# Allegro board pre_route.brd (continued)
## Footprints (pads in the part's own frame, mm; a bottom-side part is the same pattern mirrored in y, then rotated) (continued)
HDR2X2_100MIL
  round 1.651 hole 1.067: 1(0,0) 2(0,2.54) 3(2.54,0) 4(2.54,2.54)
HDR2X4_100MIL
  round 1.651 hole 1.067: 1(0,0) 2(0,2.54) 3(2.54,0) 4(2.54,2.54) 5(5.08,0) 6(5.08,2.54) 7(7.62,0) 8(7.62,2.54)
HDR2X7_100MIL
  rect 3.175x1.27 smd: 1(-2.731,7.62) 2(2.731,7.62) 3(-2.731,5.08) 4(2.731,5.08) 5(-2.731,2.54) 6(2.731,2.54) 7(-2.731,0) 8(2.731,0) 9(-2.731,-2.54) 10(2.731,-2.54) 11(-2.731,-5.08) 12(2.731,-5.08) 13(-2.731,-7.62) 14(2.731,-7.62)
HDR2X10_100MIL
  rect 3.175x1.27 smd: 1(-2.731,11.43) 2(2.731,11.43) 3(-2.731,8.89) 4(2.731,8.89) 5(-2.731,6.35) 6(2.731,6.35) 7(-2.731,3.81) 8(2.731,3.81) 9(-2.731,1.27) 10(2.731,1.27) 11(-2.731,-1.27) 12(2.731,-1.27) 13(-2.731,-3.81) 14(2.731,-3.81) 15(-2.731,-6.35) 16(2.731,-6.35) 17(-2.731,-8.89) 18(2.731,-8.89) 19(-2.731,-11.43) 20(2.731,-11.43)
HDR2X20_100MIL
  rect 3.175x1.27 smd: 1(-2.731,24.13) 2(2.731,24.13) 3(-2.731,21.59) 4(2.731,21.59) 5(-2.731,19.05) 6(2.731,19.05) 7(-2.731,16.51) 8(2.731,16.51) 9(-2.731,13.97) 10(2.731,13.97) 11(-2.731,11.43) 12(2.731,11.43) 13(-2.731,8.89) 14(2.731,8.89) 15(-2.731,6.35) 16(2.731,6.35) 17(-2.731,3.81) 18(2.731,3.81) 19(-2.731,1.27) 20(2.731,1.27) 21(-2.731,-1.27) 22(2.731,-1.27) 23(-2.731,-3.81) 24(2.731,-3.81) 25(-2.731,-6.35) 26(2.731,-6.35) 27(-2.731,-8.89) 28(2.731,-8.89) 29(-2.731,-11.43) 30(2.731,-11.43) 31(-2.731,-13.97) 32(2.731,-13.97) 33(-2.731,-16.51) 34(2.731,-16.51) 35(-2.731,-19.05) 36(2.731,-19.05) 37(-2.731,-21.59) 38(2.731,-21.59) 39(-2.731,-24.13) 40(2.731,-24.13)
HEATSINK-7106D
  custom 2.603x2.603 smd: 1(0,0)
HSSDC2
  round 0.127 hole 2.184 unplated: (-1.825,3.2) (-1.825,-3.2)
  rect 1.524x0.813 smd: 1(-10.325,3.81) 2(-10.325,2.54) 3(-10.325,1.27) 4(-10.325,0) 5(-10.325,-1.27) 6(-10.325,-2.54) 7(-10.325,-3.81)
  rect 4.013x2.54 hole 1.575: 8(-9.025,6.125) 9(-9.025,-6.125) 10(-1.825,6.125) 11(-1.825,-6.125)
  rect 3.023x3.124 hole 1.575: 12(0.975,2.6) 13(0.975,-2.6)
LQFP_32
  rect 1.905x0.457 smd: 1(-4.242,2.8) 2(-4.242,2) 3(-4.242,1.2) 4(-4.242,0.4) 5(-4.242,-0.4) 6(-4.242,-1.2) 7(-4.242,-2) 8(-4.242,-2.8) 17(4.242,-2.8) 18(4.242,-2) 19(4.242,-1.2) 20(4.242,-0.4) 21(4.242,0.4) 22(4.242,1.2) 23(4.242,2) 24(4.242,2.8)
  rect 0.457x1.905 smd: 9(-2.8,-4.242) 10(-2,-4.242) 11(-1.2,-4.242) 12(-0.4,-4.242) 13(0.4,-4.242) 14(1.2,-4.242) 15(2,-4.242) 16(2.8,-4.242) 25(2.8,4.242) 26(2,4.242) 27(1.2,4.242) 28(0.4,4.242) 29(-0.4,4.242) 30(-1.2,4.242) 31(-2,4.242) 32(-2.8,4.242)
MICTOR
  round 0.127 hole 0.813 unplated: (-15.113,-1.016) (15.113,0)
  round 0.127 hole 2.388 unplated: (11.43,0)
  rect 0.432x1.651 smd: 1(5.715,3.531) 2(5.715,-3.531) 3(5.08,3.531) 4(5.08,-3.531) 5(4.445,3.531) 6(4.445,-3.531) 7(3.81,3.531) 8(3.81,-3.531) 9(3.175,3.531) 10(3.175,-3.531) 11(2.54,3.531) 12(2.54,-3.531) 13(1.905,3.531) 14(1.905,-3.531) 15(1.27,3.531) 16(1.27,-3.531) 17(0.635,3.531) 18(0.635,-3.531) 19(0,3.531) 20(0,-3.531) 21(-0.635,3.531) 22(-0.635,-3.531) 23(-1.27,3.531) 24(-1.27,-3.531) 25(-1.905,3.531) 26(-1.905,-3.531) 27(-2.54,3.531) 28(-2.54,-3.531) 29(-3.175,3.531) 30(-3.175,-3.531) 31(-3.81,3.531) 32(-3.81,-3.531) 33(-4.445,3.531) 34(-4.445,-3.531) 35(-5.08,3.531) 36(-5.08,-3.531) 37(-5.715,3.531) 38(-5.715,-3.531)
  round 1.321 hole 0.813: 39(5.08,0) 40(2.54,0) 41(0,0) 42(-2.54,0) 43(-5.08,0)
MOLEX-10X2
  round 0.127 hole 2.997 unplated: (-42.456,5.055) (4.737,5.055)
  rect 1.905x1.905 hole 1.422: 1(0,0)
  round 1.905 hole 1.422: 2(-4.191,0) 3(-8.382,0) 4(-12.573,0) 5(-16.764,0) 6(-20.955,0) 7(-25.146,0) 8(-29.337,0) 9(-33.528,0) 10(-37.719,0) 11(0,5.512) 12(-4.191,5.512) 13(-8.382,5.512) 14(-12.573,5.512) 15(-16.764,5.512) 16(-20.955,5.512) 17(-25.146,5.512) 18(-29.337,5.512) 19(-33.528,5.512) 20(-37.719,5.512)
PACKAGE_D
  rect 2.007x1.803 smd: 1(-2.1,2.54) 2(-2.1,0) 3(-2.1,-2.54) 4(2.1,-2.54) 5(2.1,0) 6(2.1,2.54)
PQFP100_720X956
  rect 2.54x0.406 smd: 1(-8.382,9.425) 2(-8.382,8.775) 3(-8.382,8.125) 4(-8.382,7.475) 5(-8.382,6.825) 6(-8.382,6.175) 7(-8.382,5.525) 8(-8.382,4.875) 9(-8.382,4.225) 10(-8.382,3.575) 11(-8.382,2.925) 12(-8.382,2.275) 13(-8.382,1.625) 14(-8.382,0.975) 15(-8.382,0.325) 16(-8.382,-0.325) 17(-8.382,-0.975) 18(-8.382,-1.625) 19(-8.382,-2.275) 20(-8.382,-2.925) 21(-8.382,-3.575) 22(-8.382,-4.225) 23(-8.382,-4.875) 24(-8.382,-5.525) 25(-8.382,-6.175) 26(-8.382,-6.825) 27(-8.382,-7.475) 28(-8.382,-8.125) 29(-8.382,-8.775) 30(-8.382,-9.425) 51(8.382,-9.425) 52(8.382,-8.775) 53(8.382,-8.125) 54(8.382,-7.475) 55(8.382,-6.825) 56(8.382,-6.175) 57(8.382,-5.525) 58(8.382,-4.875) 59(8.382,-4.225) 60(8.382,-3.575) 61(8.382,-2.925) 62(8.382,-2.275) 63(8.382,-1.625) 64(8.382,-0.975) 65(8.382,-0.325) 66(8.382,0.325) 67(8.382,0.975) 68(8.382,1.625) 69(8.382,2.275) 70(8.382,2.925) 71(8.382,3.575) 72(8.382,4.225) 73(8.382,4.875) 74(8.382,5.525) 75(8.382,6.175) 76(8.382,6.825) 77(8.382,7.475) 78(8.382,8.125) 79(8.382,8.775) 80(8.382,9.425)
  rect 0.406x2.54 smd: 31(-6.175,-11.379) 32(-5.525,-11.379) 33(-4.875,-11.379) 34(-4.225,-11.379) 35(-3.575,-11.379) 36(-2.925,-11.379) 37(-2.275,-11.379) 38(-1.625,-11.379) 39(-0.975,-11.379) 40(-0.325,-11.379) 41(0.325,-11.379) 42(0.975,-11.379) 43(1.625,-11.379) 44(2.275,-11.379) 45(2.925,-11.379) 46(3.575,-11.379) 47(4.225,-11.379) 48(4.875,-11.379) 49(5.525,-11.379) 50(6.175,-11.379) 81(6.175,11.379) 82(5.525,11.379) 83(4.875,11.379) 84(4.225,11.379) 85(3.575,11.379) 86(2.925,11.379) 87(2.275,11.379) 88(1.625,11.379) 89(0.975,11.379) 90(0.325,11.379) 91(-0.325,11.379) 92(-0.975,11.379) 93(-1.625,11.379) 94(-2.275,11.379) 95(-2.925,11.379) 96(-3.575,11.379) 97(-4.225,11.379) 98(-4.875,11.379) 99(-5.525,11.379) 100(-6.175,11.379)
QSOP16
  rect 1.524x0.33 smd: 1(-2.413,2.223) 2(-2.413,1.587) 3(-2.413,0.953) 4(-2.413,0.318) 5(-2.413,-0.318) 6(-2.413,-0.953) 7(-2.413,-1.587) 8(-2.413,-2.223) 9(2.413,-2.223) 10(2.413,-1.587) 11(2.413,-0.953) 12(2.413,-0.318) 13(2.413,0.318) 14(2.413,0.953) 15(2.413,1.587) 16(2.413,2.223)
RES_0402
  rect 0.508x0.508 smd: 1(0,0.445) 2(0,-0.445)
RES_0603
  rect 0.813x1.067 smd: 1(0,0.85) 2(0,-0.85)
RES_0805
  rect 1.6x1.321 smd: 1(0,0.95) 2(0,-0.95)
RJ426
  round 0.127 hole 3.2 unplated: (-10.16,6.35) (1.27,6.35)
  rect 1.397x1.397 hole 0.914: 1(0,0)
  round 1.397 hole 0.914: 2(-1.27,-2.54) 3(-2.54,0) 4(-3.81,-2.54) 5(-5.08,0) 6(-6.35,-2.54) 7(-7.62,0) 8(-8.89,-2.54)
  round 1.524 hole 1.067: 9(2.184,10.414) 10(-0.356,10.414) 11(-8.534,10.414) 12(-11.074,10.414)
  round 2.083 hole 1.575: 13(-12.192,3.302) 14(3.302,3.302)
RN_SMT
  rect 0.889x0.432 smd: 1(-0.817,1.839) 8(-0.817,-1.839) 9(0.817,-1.839) 16(0.817,1.839)
  rect 0.889x0.254 smd: 2(-0.817,1.25) 3(-0.817,0.75) 4(-0.817,0.25) 5(-0.817,-0.25) 6(-0.817,-0.75) 7(-0.817,-1.25) 10(0.817,-1.25) 11(0.817,-0.75) 12(0.817,-0.25) 13(0.817,0.25) 14(0.817,0.75) 15(0.817,1.25)
RPACK8
  rect 0.889x0.432 smd: 1(-0.944,1.839) 8(-0.944,-1.839) 9(0.944,-1.839) 16(0.944,1.839)
  rect 0.889x0.254 smd: 2(-0.944,1.25) 3(-0.944,0.75) 4(-0.944,0.25) 5(-0.944,-0.25) 6(-0.944,-0.75) 7(-0.944,-1.25) 10(0.944,-1.25) 11(0.944,-0.75) 12(0.944,-0.25) 13(0.944,0.25) 14(0.944,0.75) 15(0.944,1.25)
SFP
  round 0.127 hole 1.575 unplated: (-1.4,4.1) (8.2,4.1)
  rect 0.533x2.007 smd: 1(0,0) 2(0.8,0) 3(1.6,0) 4(2.4,0) 5(3.2,0) 6(4,0) 7(4.8,0) 8(5.6,0) 9(6.4,0) 10(7.2,0) 11(6.8,8.2) 12(6,8.2) 13(5.2,8.2) 14(4.4,8.2) 15(3.6,8.2) 16(2.8,8.2) 17(2,8.2) 18(1.2,8.2) 19(0.4,8.2) 20(-0.4,8.2)
  rect 1.981x1.981 hole 1.067: 21(-3.721,-26.765) 22(4.864,-26.765) 23(10.503,-21.765) 24(-3.721,-16.765) 25(10.503,-11.765) 26(7.353,-6.765) 27(1.968,-6.765) 28(-3.721,-6.765) 31(10.503,-1.765) 37(10.503,8.235)
  round 1.473 hole 1.067: 29(-3.721,-3.965) 30(10.503,-3.965) 32(-3.721,0.735) 33(10.503,0.735) 35(-3.721,5.735) 36(10.503,5.735) 38(-1.409,10.335) 39(3.391,10.335) 40(8.191,10.335)
  rect 1.981x1.981 hole 0.914: 34(-3.721,3.235)
SMT
  round 0.127 hole 1.397 unplated: (-17.2,0) (17.2,0)
  rect 0.61x2.108 smd: 1(-15.5,-1.95) 2(-15.5,1.95) 3(-14.5,-1.95) 4(-14.5,1.95) 5(-13.5,-1.95) 6(-13.5,1.95) 7(-12.5,-1.95) 8(-12.5,1.95) 9(-11.5,-1.95) 10(-11.5,1.95) 11(-10.5,-1.95) 12(-10.5,1.95) 13(-9.5,-1.95) 14(-9.5,1.95) 15(-8.5,-1.95) 16(-8.5,1.95) 17(-7.5,-1.95) 18(-7.5,1.95) 19(-6.5,-1.95) 20(-6.5,1.95) 21(-5.5,-1.95) 22(-5.5,1.95) 23(-4.5,-1.95) 24(-4.5,1.95) 25(-3.5,-1.95) 26(-3.5,1.95) 27(-2.5,-1.95) 28(-2.5,1.95) 29(-1.5,-1.95) 30(-1.5,1.95) 31(-0.5,-1.95) 32(-0.5,1.95) 33(0.5,-1.95) 34(0.5,1.95) 35(1.5,-1.95) 36(1.5,1.95) 37(2.5,-1.95) 38(2.5,1.95) 39(3.5,-1.95) 40(3.5,1.95) 41(4.5,-1.95) 42(4.5,1.95) 43(5.5,-1.95) 44(5.5,1.95) 45(6.5,-1.95) 46(6.5,1.95) 47(7.5,-1.95) 48(7.5,1.95) 49(8.5,-1.95) 50(8.5,1.95) 51(9.5,-1.95) 52(9.5,1.95) 53(10.5,-1.95) 54(10.5,1.95) 55(11.5,-1.95) 56(11.5,1.95) 57(12.5,-1.95) 58(12.5,1.95) 59(13.5,-1.95) 60(13.5,1.95) 61(14.5,-1.95) 62(14.5,1.95) 63(15.5,-1.95) 64(15.5,1.95)
SMT_A_PROBE
  round 1.346 hole 0.813: (-14.981,2.413) (-14.981,-2.413) (14.991,-2.413)
  round 0.127 hole 0.813 unplated: (-14.981,0) (14.991,2.413)
  oval 0.584x0.711 smd: A1(-13,-1.27) A2(-12,-1.27) A3(-11,-1.27) A4(-10,-1.27) A5(-9,-1.27) A6(-8,-1.27) A7(-7,-1.27) A8(-6,-1.27) A9(-5,-1.27) A10(-4,-1.27) A11(-3,-1.27) A12(-2,-1.27) A13(-1,-1.27) A14(0,-1.27) A15(1,-1.27) A16(2,-1.27) A17(3,-1.27) A18(4,-1.27) A19(5,-1.27) A20(6,-1.27) A21(7,-1.27) A22(8,-1.27) A23(9,-1.27) A24(10,-1.27) A25(11,-1.27) A26(12,-1.27) A27(13,-1.27) B1(-13,1.27) B2(-12,1.27) B3(-11,1.27) B4(-10,1.27) B5(-9,1.27) B6(-8,1.27) B7(-7,1.27) B8(-6,1.27) B9(-5,1.27) B10(-4,1.27) B11(-3,1.27) B12(-2,1.27) B13(-1,1.27) B14(0,1.27) B15(1,1.27) B16(2,1.27) B17(3,1.27) B18(4,1.27) B19(5,1.27) B20(6,1.27) B21(7,1.27) B22(8,1.27) B23(9,1.27) B24(10,1.27) B25(11,1.27) B26(12,1.27) B27(13,1.27)
SO8
  oval 2.032x0.635 smd: 1(-2.54,1.905) 2(-2.54,0.635) 3(-2.54,-0.635) 4(-2.54,-1.905) 5(2.54,-1.905) 6(2.54,-0.635) 7(2.54,0.635) 8(2.54,1.905)
SO8N
  rect 0.584x2.184 smd: 1(0,-2.608) 2(1.27,-2.608) 3(2.54,-2.608) 4(3.81,-2.608) 5(3.81,2.608) 6(2.54,2.608) 7(1.27,2.608) 8(0,2.608)
SO24
  rect 2.184x0.813 smd: 1(-4.801,6.985) 2(-4.801,5.715) 3(-4.801,4.445) 4(-4.801,3.175) 5(-4.801,1.905) 6(-4.801,0.635) 7(-4.801,-0.635) 8(-4.801,-1.905) 9(-4.801,-3.175) 10(-4.801,-4.445) 11(-4.801,-5.715) 12(-4.801,-6.985) 13(4.801,-6.985) 14(4.801,-5.715) 15(4.801,-4.445) 16(4.801,-3.175) 17(4.801,-1.905) 18(4.801,-0.635) 19(4.801,0.635) 20(4.801,1.905) 21(4.801,3.175) 22(4.801,4.445) 23(4.801,5.715) 24(4.801,6.985)
SO40
  rect 1.803x0.305 smd: 1(-2.7,4.75) 2(-2.7,4.25) 3(-2.7,3.75) 4(-2.7,3.25) 5(-2.7,2.75) 6(-2.7,2.25) 7(-2.7,1.75) 8(-2.7,1.25) 9(-2.7,0.75) 10(-2.7,0.25) 11(-2.7,-0.25) 12(-2.7,-0.75) 13(-2.7,-1.25) 14(-2.7,-1.75) 15(-2.7,-2.25) 16(-2.7,-2.75) 17(-2.7,-3.25) 18(-2.7,-3.75) 19(-2.7,-4.25) 20(-2.7,-4.75) 21(2.7,-4.75) 22(2.7,-4.25) 23(2.7,-3.75) 24(2.7,-3.25) 25(2.7,-2.75) 26(2.7,-2.25) 27(2.7,-1.75) 28(2.7,-1.25) 29(2.7,-0.75) 30(2.7,-0.25) 31(2.7,0.25) 32(2.7,0.75) 33(2.7,1.25) 34(2.7,1.75) 35(2.7,2.25) 36(2.7,2.75) 37(2.7,3.25) 38(2.7,3.75) 39(2.7,4.25) 40(2.7,4.75)
SOG_05
  rect 1.499x0.305 smd: 1(-2.036,1) 2(-2.036,0.5) 3(-2.036,0) 4(-2.036,-0.5) 5(-2.036,-1) 6(2.036,-1) 7(2.036,-0.5) 8(2.036,0) 9(2.036,0.5) 10(2.036,1)
SOG_50
  rect 2.21x0.61 smd: 1(-2.6,4.445) 2(-2.6,3.175) 3(-2.6,1.905) 4(-2.6,0.635) 5(-2.6,-0.635) 6(-2.6,-1.905) 7(-2.6,-3.175) 8(-2.6,-4.445) 9(2.6,-4.445) 10(2.6,-3.175) 11(2.6,-1.905) 12(2.6,-0.635) 13(2.6,0.635) 14(2.6,1.905) 15(2.6,3.175) 16(2.6,4.445)
SOG_65
  rect 2.032x0.635 smd: 1(-2.794,1.905) 2(-2.794,0.635) 3(-2.794,-0.635) 4(-2.794,-1.905) 5(2.794,-1.905) 6(2.794,-0.635) 7(2.794,0.635) 8(2.794,1.905)
SOIC8
  rect 2.032x0.635 smd: 1(-2.794,1.905) 2(-2.794,0.635) 3(-2.794,-0.635) 4(-2.794,-1.905) 5(2.794,-1.905) 6(2.794,-0.635) 7(2.794,0.635) 8(2.794,1.905)
SOIC16F
  oval 2.032x0.635 smd: 1(-3.81,4.445) 2(-3.81,3.175) 3(-3.81,1.905) 4(-3.81,0.635) 5(-3.81,-0.635) 6(-3.81,-1.905) 7(-3.81,-3.175) 8(-3.81,-4.445) 9(3.81,-4.445) 10(3.81,-3.175) 11(3.81,-1.905) 12(3.81,-0.635) 13(3.81,0.635) 14(3.81,1.905) 15(3.81,3.175) 16(3.81,4.445)
SOIC20
  rect 2.21x0.61 smd: 1(-4.477,5.715) 2(-4.477,4.445) 3(-4.477,3.175) 4(-4.477,1.905) 5(-4.477,0.635) 6(-4.477,-0.635) 7(-4.477,-1.905) 8(-4.477,-3.175) 9(-4.477,-4.445) 10(-4.477,-5.715) 11(4.477,-5.715) 12(4.477,-4.445) 13(4.477,-3.175) 14(4.477,-1.905) 15(4.477,-0.635) 16(4.477,0.635) 17(4.477,1.905) 18(4.477,3.175) 19(4.477,4.445) 20(4.477,5.715)
SOT23-5
  rect 1.016x0.508 smd: 1(-1.321,0.95) 2(-1.321,0) 3(-1.321,-0.95) 4(1.321,-0.95) 5(1.321,0.95)
SSOT6
  oval 1.778x0.508 smd: 1(-1.143,0.95) 2(-1.143,0) 3(-1.143,-0.95) 4(1.143,-0.95) 5(1.143,0) 6(1.143,0.95)
TEK_PROBE
  round 0.127 hole 3.505 unplated: (-12.84,0) (12.814,0)
  round 0.127 hole 1.702 unplated: (9.131,1.143)
  rect 0.406x0.813 smd: A1(7.556,-1.575) A2(6.642,-1.575) A3(5.728,-1.575) A4(3.899,-1.575) A5(2.985,-1.575) A6(2.07,-1.575) A7(0.241,-1.575) A8(-0.673,-1.575) A9(-1.587,-1.575) A10(-3.416,-1.575) A11(-4.331,-1.575) A12(-5.245,-1.575) A13(-7.074,-1.575) A14(-7.988,-1.575) A15(-8.903,-1.575) B1(5.22,1.575) B2(4.305,1.575) B3(3.391,1.575) B4(1.562,1.575) B5(0.648,1.575) B6(-0.267,1.575) B7(-2.095,1.575) B8(-3.01,1.575) B9(-3.924,1.575) B10(-5.753,1.575) B11(-6.668,1.575) B12(-7.582,1.575)
TH-CONN-2-P1
  rect 1.524x1.524 hole 1.067: 1(0,0)
  round 1.524 hole 1.067: 2(2.54,0)
THRU_HOLE
  rect 2.819x2.769 smd: 1(0,3.15) 2(0,-3.15)
TO263
  rect 1.067x2.159 smd: 1(-2.54,-8.319) 2(0,-8.319) 3(2.54,-8.319)
  rect 10.795x10.414 smd: 4(0,0)
TO263_5
  rect 5.08x1.143 smd: 1(-8.052,3.404) 2(-8.052,1.702) 3(-8.052,0) 4(-8.052,-1.702) 5(-8.052,-3.404)
  rect 10.414x10.795 smd: 6(1.092,0)
TQFP128P
  round 1.016 smd: (0,0)
  rect 1.778x0.254 smd: 1(-7.5,6.2) 2(-7.5,5.8) 3(-7.5,5.4) 4(-7.5,5) 5(-7.5,4.6) 6(-7.5,4.2) 7(-7.5,3.8) 8(-7.5,3.4) 9(-7.5,3) 10(-7.5,2.6) 11(-7.5,2.2) 12(-7.5,1.8) 13(-7.5,1.4) 14(-7.5,1) 15(-7.5,0.6) 16(-7.5,0.2) 17(-7.5,-0.2) 18(-7.5,-0.6) 19(-7.5,-1) 20(-7.5,-1.4) 21(-7.5,-1.8) 22(-7.5,-2.2) 23(-7.5,-2.6) 24(-7.5,-3) 25(-7.5,-3.4) 26(-7.5,-3.8) 27(-7.5,-4.2) 28(-7.5,-4.6) 29(-7.5,-5) 30(-7.5,-5.4) 31(-7.5,-5.8) 32(-7.5,-6.2) 65(7.5,-6.2) 66(7.5,-5.8) 67(7.5,-5.4) 68(7.5,-5) 69(7.5,-4.6) 70(7.5,-4.2) 71(7.5,-3.8) 72(7.5,-3.4) 73(7.5,-3) 74(7.5,-2.6) 75(7.5,-2.2) 76(7.5,-1.8) 77(7.5,-1.4) 78(7.5,-1) 79(7.5,-0.6) 80(7.5,-0.2) 81(7.5,0.2) 82(7.5,0.6) 83(7.5,1) 84(7.5,1.4) 85(7.5,1.8) 86(7.5,2.2) 87(7.5,2.6) 88(7.5,3) 89(7.5,3.4) 90(7.5,3.8) 91(7.5,4.2) 92(7.5,4.6) 93(7.5,5) 94(7.5,5.4) 95(7.5,5.8) 96(7.5,6.2)
  rect 0.254x1.778 smd: 33(-6.2,-7.5) 34(-5.8,-7.5) 35(-5.4,-7.5) 36(-5,-7.5) 37(-4.6,-7.5) 38(-4.2,-7.5) 39(-3.8,-7.5) 40(-3.4,-7.5) 41(-3,-7.5) 42(-2.6,-7.5) 43(-2.2,-7.5) 44(-1.8,-7.5) 45(-1.4,-7.5) 46(-1,-7.5) 47(-0.6,-7.5) 48(-0.2,-7.5) 49(0.2,-7.5) 50(0.6,-7.5) 51(1,-7.5) 52(1.4,-7.5) 53(1.8,-7.5) 54(2.2,-7.5) 55(2.6,-7.5) 56(3,-7.5) 57(3.4,-7.5) 58(3.8,-7.5) 59(4.2,-7.5) 60(4.6,-7.5) 61(5,-7.5) 62(5.4,-7.5) 63(5.8,-7.5) 64(6.2,-7.5) 97(6.2,7.5) 98(5.8,7.5) 99(5.4,7.5) 100(5,7.5) 101(4.6,7.5) 102(4.2,7.5) 103(3.8,7.5) 104(3.4,7.5) 105(3,7.5) 106(2.6,7.5) 107(2.2,7.5) 108(1.8,7.5) 109(1.4,7.5) 110(1,7.5) 111(0.6,7.5) 112(0.2,7.5) 113(-0.2,7.5) 114(-0.6,7.5) 115(-1,7.5) 116(-1.4,7.5) 117(-1.8,7.5) 118(-2.2,7.5) 119(-2.6,7.5) 120(-3,7.5) 121(-3.4,7.5) 122(-3.8,7.5) 123(-4.2,7.5) 124(-4.6,7.5) 125(-5,7.5) 126(-5.4,7.5) 127(-5.8,7.5) 128(-6.2,7.5)
TSM-105-01-L-DV
  rect 3.81x1.27 smd: 1(-2.54,5.08) 2(2.54,5.08) 3(-2.54,2.54) 4(2.54,2.54) 5(-2.54,0) 6(2.54,0) 7(-2.54,-2.54) 8(2.54,-2.54) 9(-2.54,-5.08) 10(2.54,-5.08)
TSM-110-01-G-DV
  rect 3.81x1.27 smd: 1(-2.54,11.43) 2(2.54,11.43) 3(-2.54,8.89) 4(2.54,8.89) 5(-2.54,6.35) 6(2.54,6.35) 7(-2.54,3.81) 8(2.54,3.81) 9(-2.54,1.27) 10(2.54,1.27) 11(-2.54,-1.27) 12(2.54,-1.27) 13(-2.54,-3.81) 14(2.54,-3.81) 15(-2.54,-6.35) 16(2.54,-6.35) 17(-2.54,-8.89) 18(2.54,-8.89) 19(-2.54,-11.43) 20(2.54,-11.43)
TSOP48
  rect 1.778x0.305 smd: 1(-9.5,5.75) 2(-9.5,5.25) 3(-9.5,4.75) 4(-9.5,4.25) 5(-9.5,3.75) 6(-9.5,3.25) 7(-9.5,2.75) 8(-9.5,2.25) 9(-9.5,1.75) 10(-9.5,1.25) 11(-9.5,0.75) 12(-9.5,0.25) 13(-9.5,-0.25) 14(-9.5,-0.75) 15(-9.5,-1.25) 16(-9.5,-1.75) 17(-9.5,-2.25) 18(-9.5,-2.75) 19(-9.5,-3.25) 20(-9.5,-3.75) 21(-9.5,-4.25) 22(-9.5,-4.75) 23(-9.5,-5.25) 24(-9.5,-5.75) 25(9.5,-5.75) 26(9.5,-5.25) 27(9.5,-4.75) 28(9.5,-4.25) 29(9.5,-3.75) 30(9.5,-3.25) 31(9.5,-2.75) 32(9.5,-2.25) 33(9.5,-1.75) 34(9.5,-1.25) 35(9.5,-0.75) 36(9.5,-0.25) 37(9.5,0.25) 38(9.5,0.75) 39(9.5,1.25) 40(9.5,1.75) 41(9.5,2.25) 42(9.5,2.75) 43(9.5,3.25) 44(9.5,3.75) 45(9.5,4.25) 46(9.5,4.75) 47(9.5,5.25) 48(9.5,5.75)
TSSOP8
  oval 1.778x0.381 smd: 1(-2.921,0.975) 2(-2.921,0.325) 3(-2.921,-0.325) 4(-2.921,-0.975) 5(2.921,-0.975) 6(2.921,-0.325) 7(2.921,0.325) 8(2.921,0.975)
TSSOP20
  rect 1.651x0.356 smd: 1(-2.781,2.925) 2(-2.781,2.275) 3(-2.781,1.625) 4(-2.781,0.975) 5(-2.781,0.325) 6(-2.781,-0.325) 7(-2.781,-0.975) 8(-2.781,-1.625) 9(-2.781,-2.275) 10(-2.781,-2.925) 11(2.781,-2.925) 12(2.781,-2.275) 13(2.781,-1.625) 14(2.781,-0.975) 15(2.781,-0.325) 16(2.781,0.325) 17(2.781,0.975) 18(2.781,1.625) 19(2.781,2.275) 20(2.781,2.925)
TSSOP48
  rect 1.905x0.305 smd: 1(-3.641,5.75) 2(-3.641,5.25) 3(-3.641,4.75) 4(-3.641,4.25) 5(-3.641,3.75) 6(-3.641,3.25) 7(-3.641,2.75) 8(-3.641,2.25) 9(-3.641,1.75) 10(-3.641,1.25) 11(-3.641,0.75) 12(-3.641,0.25) 13(-3.641,-0.25) 14(-3.641,-0.75) 15(-3.641,-1.25) 16(-3.641,-1.75) 17(-3.641,-2.25) 18(-3.641,-2.75) 19(-3.641,-3.25) 20(-3.641,-3.75) 21(-3.641,-4.25) 22(-3.641,-4.75) 23(-3.641,-5.25) 24(-3.641,-5.75) 25(3.641,-5.75) 26(3.641,-5.25) 27(3.641,-4.75) 28(3.641,-4.25) 29(3.641,-3.75) 30(3.641,-3.25) 31(3.641,-2.75) 32(3.641,-2.25) 33(3.641,-1.75) 34(3.641,-1.25) 35(3.641,-0.75) 36(3.641,-0.25) 37(3.641,0.25) 38(3.641,0.75) 39(3.641,1.25) 40(3.641,1.75) 41(3.641,2.25) 42(3.641,2.75) 43(3.641,3.25) 44(3.641,3.75) 45(3.641,4.25) 46(3.641,4.75) 47(3.641,5.25) 48(3.641,5.75)
TSSOP_8
  rect 1.524x0.406 smd: 1(-2.095,0.975) 2(-2.095,0.325) 3(-2.095,-0.325) 4(-2.095,-0.975) 5(2.095,-0.975) 6(2.095,-0.325) 7(2.095,0.325) 8(2.095,0.975)
unnamed#2
  round 1.27 smd: (0,0)
VERT_SM_SMA
  round 1.702 smd: 1(0,0)
  round 2.083 hole 1.575: 2(-2.54,2.54) 3(2.54,2.54) 4(-2.54,-2.54) 5(2.54,-2.54)
XPAK1
  round 2.54 hole 1.575: (-19.05,0) (-19.05,-11.43) (-19.05,-24.13) (-19.05,-36.83) (-19.05,-49.53) (19.05,3.81) (19.05,-17.78) (19.05,-30.48) (19.05,-43.18) (19.05,-55.88)
  round 0.127 hole 1.575 unplated: (-14.8,0) (14.8,0)
  rect 0.508x2.032 smd: 1(-13.4,-4.1) 2(-12.6,-4.1) 3(-11.8,-4.1) 4(-11,-4.1) 5(-10.2,-4.1) 6(-9.4,-4.1) 7(-8.6,-4.1) 8(-7.8,-4.1) 9(-7,-4.1) 10(-6.2,-4.1) 11(-5.4,-4.1) 12(-4.6,-4.1) 13(-3.8,-4.1) 14(-3,-4.1) 15(-2.2,-4.1) 16(-1.4,-4.1) 17(-0.6,-4.1) 18(0.2,-4.1) 19(1,-4.1) 20(1.8,-4.1) 21(2.6,-4.1) 22(3.4,-4.1) 23(4.2,-4.1) 24(5,-4.1) 25(5.8,-4.1) 26(6.6,-4.1) 27(7.4,-4.1) 28(8.2,-4.1) 29(9,-4.1) 30(9.8,-4.1) 31(10.6,-4.1) 32(11.4,-4.1) 33(12.2,-4.1) 34(13,-4.1) 35(13.8,-4.1) 36(13.4,4.1) 37(12.6,4.1) 38(11.8,4.1) 39(11,4.1) 40(10.2,4.1) 41(9.4,4.1) 42(8.6,4.1) 43(7.8,4.1) 44(7,4.1) 45(6.2,4.1) 46(5.4,4.1) 47(4.6,4.1) 48(3.8,4.1) 49(3,4.1) 50(2.2,4.1) 51(1.4,4.1) 52(0.6,4.1) 53(-0.2,4.1) 54(-1,4.1) 55(-1.8,4.1) 56(-2.6,4.1) 57(-3.4,4.1) 58(-4.2,4.1) 59(-5,4.1) 60(-5.8,4.1) 61(-6.6,4.1) 62(-7.4,4.1) 63(-8.2,4.1) 64(-9,4.1) 65(-9.8,4.1) 66(-10.6,4.1) 67(-11.4,4.1) 68(-12.2,4.1) 69(-13,4.1) 70(-13.8,4.1)

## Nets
1.5V_A_INT: C19.1 HS2.1(HS1) R6.1 U2.2(VO) U2.4
1.5V_ENABLE: C143.1 J113.2 U36.2
1.5V_GX_INT: C34.2 C36.2 C37.2 C38.1 C39.1 C40.1 C49.1 C128.1 C148.1 C149.2 C150.2 C151.2 C152.1 C153.1 C154.1 C155.1 C156.1 C157.1 C158.1 C159.1 C160.1 C161.1 C162.1 C163.1 C164.1 C165.1 C166.1 C171.1 C172.1 C173.2 C174.2 C175.2 C176.2 C177.2 C178.2 C179.2 C180.2 C181.2 C182.2 C183.2 C184.2 C185.2 C186.2 C187.2 C188.2 C189.2 C190.2 C191.2 C192.2 C193.2 C194.2 C195.2 C196.1 C197.1 C198.1 C199.2 C200.1 C201.1 C211.2 C212.2 C213.2 C214.1 C215.1 C216.1 C217.2 C218.1 C219.2 C220.1 C226.1 C227.2 C228.1 C241.1 C245.1 C246.1 C247.2 C248.1 C250.1 C251.1 C253.1 C255.1 C256.2 C257.1 C258.1 C260.1 C261.2 C262.1 C264.1 C265.1 C267.2 C268.1 C269.1 C272.1 C273.1 C274.2 C275.2 C276.1 C277.2 C285.2 C289.2 C296.2 C298.1 C302.1 C305.2 C306.2 C311.1 C312.1 C320.2 C321.1 C323.2 C327.2 C330.2 C335.2 C338.2 C342.2 C343.2 C348.2 C349.2 C354.2 C356.2 C391.2 C393.1 C395.1 C396.2 C397.1 C746.1 C787.1 R249.2 R250.2 R251.2 R252.2 R253.2 R254.2 R255.2 R256.2 R257.2 R258.2 R330.2 R331.2 R332.2 R333.2
1.5V_OUT: C28.1 U36.4 U36.5
1.5V_PLL: C45.1 C46.1 C47.1 C287.2 C295.2 C314.1 C329.1 C364.1 C365.1 C366.1 C370.2 C371.2 C374.1 C375.2 C378.1 C379.2 C381.1 C385.1 C386.2 C400.1 C401.1 C409.2 C410.1 C411.1 C412.1 C413.1 C438.1 C459.1 C463.1 C469.1 C470.2 C480.2 C481.1 C533.1 C537.2 C541.2 C544.1 C559.1 C586.1 C593.2 C594.2 C602.1 C603.2 C604.2 C610.1 C611.1 C616.1 C627.1 C698.1 U15.AG16 U15.AG17 U15.AJ2 U15.AJ31 U15.D2 U15.D31 U15.E16 U15.G17 U15.T8 U15.T25 U15.U8 U15.U25
1.5V_S_INT: C126.1 C439.1 C440.1 C441.2 C442.2 C443.2 C444.2 C445.2 C446.2 C447.2 C448.2 C449.2 C450.2 C451.2 C452.1 C453.1 C454.2 C455.2 C456.2 C457.1 C458.1 C465.2 C466.2 C471.2 C472.2 C474.2 C475.2 C476.2 C477.2 C483.2 C484.2 C487.2 C488.2 C491.2 C492.1 C494.2 C498.1 C499.2 C500.1 C501.2 C503.1 C504.1 C507.2 C508.2 C511.1 C512.2 C513.1 C514.2 C515.2 C516.2 C517.1 C520.1 C521.2 C523.1 C525.2 C527.2 C528.2 C529.1 C530.1 C534.1 C536.2 C538.1 C539.2 C542.1 C545.2 C546.2 C547.2 C548.1 C549.1 C550.1 C552.2 C554.1 C556.1 C557.1 C558.1 C560.1 C561.1 C562.1 C563.1 C565.2 C566.2 C568.1 C569.1 C570.1 C571.2 C573.1 C574.2 C576.1 C577.1 C579.2 C580.1 C581.1 C583.1 C584.2 C585.1 C591.1 C592.1 C596.1 C597.1 C599.2 C600.2 C605.1 C606.2 C608.2 C609.2 C614.1 C615.2 C617.2 C618.1 C619.1 C620.1 C621.2 C622.2 C623.1 C624.1 C625.1 C626.1 C628.2 C629.1 C630.1 C631.1 C632.1 C633.2 C634.1 C635.1 C636.1 C637.1 C786.1 U15.AD16 U15.AF16 U15.AJ3 U15.AJ30 U15.D3 U15.D30 U15.H16 U15.J16 U15.M12 U15.M14 U15.M19 U15.M21 U15.N13 U15.N15 U15.N18 U15.N20 U15.P12 U15.P14 U15.P16 U15.P17 U15.P19 U15.P21 U15.R13 U15.R15 U15.R18 U15.R20 U15.R22 U15.T9 U15.T14 U15.T16 U15.T17 U15.T19 U15.U14 U15.U16 U15.U17 U15.U19 U15.U24 U15.V11 U15.V13 U15.V15 U15.V18 U15.V20 U15.W14 U15.W16 U15.W17 U15.W19 U15.Y13 U15.Y15 U15.Y18 U15.Y20
1.5V_VCCP: C778.2 C779.2 C780.2 C781.2
1.5V_XCVR: C33.1 C35.2 C136.2 C137.1 C138.2 C139.2 C204.2 C205.2 C206.2 C207.2 C229.1 C230.2 C231.2 C243.1 C249.1 C252.1 C286.2 C290.2 C303.1 C322.2 C326.1 C355.2 C360.1 C372.1 C373.1 C384.1 C387.2 C399.1 C402.1 C403.2 C427.1 C428.1 C699.1 C788.1 C789.1
1.5V_XCVR1: C754.2 C755.2 C756.2 C757.2
1.5V_XCVR2: C758.2 C759.2 C760.2 C761.2
1.5V_XCVR3: C762.2 C763.2 C764.2 C765.2
1.5V_XCVR4: C766.2 C767.2 C768.2 C769.2
1.5V_XCVR5: C770.2 C771.2 C772.2 C773.2
1.8V_DDR: XU2.51 XU2.53 XU2.56 XU2.59 XU2.62 XU2.64 XU2.67 XU2.69 XU2.72 XU2.75 XU2.78 XU2.170 XU2.172 XU2.175 XU2.178 XU2.181 XU2.184 XU2.187 XU2.189 XU2.191 XU2.194 XU2.197 XU2.238
1.25V: C716.1 C717.1
1.25VREF: C719.1 R324.1 U53.4
2.5V: C697.1 C714.1 C785.1 R326.1 U53.6 U53.7
2.5V_DDR_VDD: C129.1 C130.2 C132.1 C135.2 C140.1 C141.2 C142.2 C144.1 C168.2 C169.1 C202.1 C203.1 C208.2 C233.1 C234.1 C237.2 C242.1 C259.2 C263.2 C266.1 C270.1 C291.2 C292.2 C299.1 C300.1 C324.2 C331.2 C332.1 C341.1 C350.2 C359.2 C361.1 C362.1 C416.2 C417.2 C419.1 C420.1 C431.2 C432.1 C434.2 C435.2 C436.1 C437.1 C460.2 C461.2 C462.1 C489.1 C490.2 C519.2 C524.1
2.5V_ENABLE: J112.2 R299.1 U1.1
2.5V_GX_IO: C235.1 C271.1 C279.1 C284.1 C288.1 C316.1 C319.1 C346.1 C696.1 C784.1
2.5V_OUT: C14.2 C15.2 R4.1 U1.4
2.5V_REG_IN: C9.1 R2.1 R299.2 U1.2
3.3V: C51.1 C53.1 C58.1 C59.1 C62.1 C63.1 C64.1 C65.1 C66.2 C67.2 C68.2 C69.2 C70.1 C71.1 C72.1 C74.1 C75.1 C78.1 C79.1 C80.1 C93.1 C423.1 C424.1 C496.1 C497.1 C646.1 C652.1 C655.1 C660.1 C662.1 C665.1 C666.1 C669.1 C670.1 C671.1 C673.1 C674.1 C682.1 C749.1 C750.1 C751.1 C752.1 C753.1 J63.4 J78.5 J78.7 J85.4 J85.6 J87.4 J87.6 PMCJN1.12 PMCJN1.19 PMCJN1.31 PMCJN1.41 PMCJN1.45 PMCJN1.57(V4_IO) PMCJN2.12 PMCJN2.15 PMCJN2.24 PMCJN2.27 PMCJN2.36 PMCJN2.41 PMCJN2.50 PMCJN2.53 PMCJN2.62 R37.2 R41.2 R42.2 R44.2 R51.2 R55.2 R57.2 R65.2 R66.2 R67.2 R68.2 R80.2 R81.2 R82.2 R83.2 R84.2 R85.2 R98.2 R99.2 R100.2 R119.2 R123.2 R124.1 R133.2 R134.2 R140.1 R142.2 R143.2 R144.2 R145.2 R146.2 R147.2 R148.2 R158.2 R160.2 R161.1 R162.1 R173.1 R174.1 R175.2 R204.1 R205.1 R206.1 R209.1 R210.1 R211.1 R217.1 R218.1 R219.1 R220.1 R221.1 R224.1 R226.1 R227.1 R228.1 R229.1 R230.1 R231.2 R232.2 R233.2 R235.1 R237.1 R239.1 R241.1 R278.1 R279.2 R280.2 R281.2 R289.2 R290.2 R291.2 R292.2 R293.2 R294.2 R303.2 R304.2 R305.2 R358.1 R359.1 R360.1 RN14.1 RN14.2 RN14.3 RN14.4 RN14.5 RN14.6 RN14.7 RN14.8 RN37.1 RN37.2 RN37.3 RN37.4 RN37.5 RN37.6 RN37.7 RN37.8 RN38.1 RN38.2 RN38.3 RN38.4 RN38.5 RN38.6 RN38.7 RN38.8 RN39.1 RN39.2 U19.30 U19.40(VCC2) U20.30 U20.40(VCC2) U21.30 U21.40(VCC2) U25.7 U25.18 U25.31 U25.42(VCC4) U26.7 U26.18 U26.31 U26.42(VCC4) U29.5 U29.12 U29.22 U29.40 U29.43 U29.45(WP*) U29.59 U29.61 U29.67 U29.68 U29.92 U30.5 U30.12 U30.22 U30.40 U30.43 U30.45(WP*) U30.59 U30.61 U30.67 U30.68 U30.92 U31.37 U34.7 U34.18 U34.31 U34.42(VCC4) U43.16 U44.16
3.3V_CLK1: C518.1 C684.1 C685.1 C686.1 C747.1 R15.1 R87.1 R90.1 R172.2 R195.1 U32.2 U32.8 U32.10 U32.18(VDD2) U46.8 Y3.4(VCC)
3.3V_CLK2: C532.1 C687.1 C721.1 C722.1 C748.1 R91.1 R94.1 R159.2 R192.1 R193.1 U18.2 U18.8 U18.10 U18.18(VDD2) U47.8 Y2.4(VCC)
3.3V_CLK3: C526.1 C643.1 C694.1 C695.1 R260.2 U13.1(VDDO) U13.2 Y1.4(VCC)
3.3V_DIV: C661.2 C663.2 C664.2 C692.1 C693.1 R19.2 R28.2 R31.2 R355.2 U4.8 U6.1 U6.8 U6.20
3.3V_ENABLE: J111.2 R296.1 U42.1
3.3V_EXT_CLK: C421.1 C422.1 C426.1 C429.1 C653.1 C745.1 R74.1 R75.1 U10.2 U10.9 U10.13 U10.17(VDDC3) U10.18 U10.22 U10.25 U10.29
3.3V_FAN_OUT: C73.1 U37.4 U37.5
3.3V_GX_IO: C54.1 C55.1 C56.1 C278.2 C281.1 C283.1 C301.1 C304.1 C309.1 C310.2 C315.1 C318.2 C333.1 C334.1 C336.2 C337.1 C340.2 C345.2 C347.1 C351.1 C353.2 C367.1 C368.2 C369.1 C376.1 C377.1 C380.1 C382.1 C383.1 C388.1 C389.1 C390.1 C394.1 C404.1 C405.1 C406.1 C407.1 C408.1 C414.1 C415.1 C683.1 C783.1
3.3V_GX_XCVR_AND_CLOCKS: C680.1 R297.2 U42.4
3.3V_LAN: C83.1 C667.1 C668.1 C672.1 C690.1 C691.1 R121.2 R243.2 R244.2 RJ1.9 RJ1.11 U11.1 U11.11 U11.16 U11.33 U11.44 U11.62 U11.77 U11.98 U11.110 U11.120 Y4.6(VCC)
3.3V_PLL: C84.1 C85.1 C89.1 C91.1 U15.AB17 U15.AE17 U15.H17 U15.L17
3.3V_PS: C57.1 C357.1 C358.1
3.3V_REF: C398.1 R187.1 R222.2 U37.16 U38.3(OUT)
3.3V_RS232: C495.1 C540.1 R163.1 R164.1 R169.1 R170.1 U28.16(VCC) U33.16(VCC)
3.3V_S_IO: C467.1 C468.1 C473.1 C478.1 C479.1 C482.1 C485.1 C486.1 C502.1 C505.1 C506.1 C509.1 C510.1 C522.1 C531.1 C535.1 C543.1 C551.1 C553.1 C555.1 C572.1 C575.1 C578.1 C582.1 C589.1 C590.1 C595.1 C598.1 C601.1 C607.1 C612.1 C613.1 C681.1 C782.1 R131.2 U15.A3 U15.A12 U15.A21 U15.A30 U15.AA1 U15.AA32 U15.AC16 U15.AC17 U15.AK1 U15.AK2 U15.AK31 U15.AK32 U15.AM3 U15.AM12 U15.AM21 U15.AM30 U15.C1 U15.C2 U15.C31 U15.C32 U15.K16 U15.K17 U15.M1 U15.M32 U15.T10 U15.T23 U15.U10 U15.U23
3.3V_S_IOB: C728.1
3.3V_TEL: R351.1 U8.4
3.3V_XCVR_CLKS: C41.1 C43.1 C44.1 C209.1 C210.1 C236.1 C240.1 C244.1 C701.1
3.3V_XPAK: C16.1 C689.1 U27.5 U27.6 U27.30 U27.31
3.3VIO_ENABLE: C317.1 J114.2 U37.2
3.3VM: C122.1 C123.1 C145.1 C146.1 R2.2 U2.3
3.3VM_ATX: J31.1 J31.2 J31.11
5V_CF: C711.1 C712.1 C713.1 C774.2 CON3.13 CON3.38 U59.2 U59.3(VOUT2)
5V_TEL: U8.7
5V_XPAK: C13.1 C688.1 U27.4 U27.32
5VM: C120.1 C121.1 C170.1 C254.1 C293.1 C294.1 C325.1 C339.1 C344.1 C392.1 C678.1 C679.1 PMCJN1.8 PMCJN1.18 PMCJN1.30 PMCJN1.38 PMCJN1.50 PMCJN1.62 R189.1 R215.1 R296.2 R318.1 R319.1 R344.1 R352.1 U42.2 U59.4
5VM_ATX: J31.4 J31.6 J31.19 J31.20
12V_DIV: C776.1 R354.2 U60.5(OUT)
12V_TEL: U45.7 U45.8
12VM: C76.1 C110.1 C131.1 J78.1 PMCJN2.1 R300.1 R301.1 R361.2
12VM_ATX: J31.10
-12VM: C26.1 C27.1 C61.1 J31.12 PMCJN1.2
-48V_IN: C48.2
-48V_ONN: ISO1.8 U8.2 U45.2
-48V_PWR: C100.2 C124.2 ISO1.2 ISO1.7 R216.1 U8.3(VIN_ORBR_-_CRBR_) U45.3(VIN_ORBR_-_CRBR_)
GND: C9.2 C12.2 C13.2 C14.1 C15.1 C16.2 C26.2 C27.2 C28.2 C34.1 C36.1 C37.1 C38.2 C39.2 C40.2 C42.2 C49.2 C54.2 C55.2 C56.2 C57.2 C58.2 C59.2 C61.2 C62.2 C63.2 C64.2 C65.2 C66.1 C67.1 C68.1 C69.1 C70.2 C71.2 C73.2 C74.2 C75.2 C76.2 C78.2 C79.2 C81.2 C82.2 C86.2 C87.2 C88.2 C90.2 C93.2 C95.2 C102.2 C103.1 C110.2 C111.2 C114.2 C116.2 C119.2 C120.2 C121.2 C122.2 C123.2 C126.2 C128.2 C129.2 C130.1 C131.2 C132.2 C133.2 C134.2 C135.1 C140.2 C141.1 C142.1 C143.2 C144.2 C145.2 C146.2 C147.2 C148.2 C149.1 C150.1 C151.1 C152.2 C153.2 C154.2 C155.2 C156.2 C157.2 C158.2 C159.2 C160.2 C161.2 C162.2 C163.2 C164.2 C165.2 C166.2 C167.2 C168.1 C169.2 C170.2 C171.2 C172.2 C173.1 C174.1 C175.1 C176.1 C177.1 C178.1 C179.1 C180.1 C181.1 C182.1 C183.1 C184.1 C185.1 C186.1 C187.1 C188.1 C189.1 C190.1 C191.1 C192.1 C193.1 C194.1 C195.1 C196.2 C197.2 C198.2 C199.1 C200.2 C201.2 C202.2 C203.2 C208.1 C211.1 C212.1 C213.1 C214.2 C215.2 C216.2 C217.1 C218.2 C219.1 C220.2 C226.2 C227.1 C228.2 C232.2 C233.2 C234.2 C235.2 C237.1 C238.2 C239.2 C241.2 C242.2 C245.2 C246.2 C247.1 C248.2 C250.2 C251.2 C253.2 C254.2 C255.2 C256.1 C257.2 C258.2 C259.1 C260.2 C261.1 C262.2 C263.1 C264.2 C265.2 C266.2 C267.1 C268.2 C269.2 C270.2 C271.2 C272.2 C273.2 C274.1 C275.1 C276.2 C277.1 C278.1 C279.2 C280.2 C281.2 C283.2 C284.2 C285.1 C288.2 C289.1 C291.1 C292.1 C293.2 C294.2 C296.1 C298.2 C299.2 C300.2 C301.2 C302.2 C304.2 C305.1 C306.1 C307.2 C308.2 C309.2 C310.1 C311.2 C312.2 C313.2 C315.2 C316.2 C317.2 C318.1 C319.2 C320.1 C321.2 C323.1 C324.1 C325.2 C327.1 C328.2 C330.1 C331.1 C332.2 C333.2 C334.2 C335.1 C336.1 C337.2 C338.1 C339.2 C340.1 C341.2 C342.1 C343.1 C344.2 C345.1 C346.2 C347.2 C348.1 C349.1 C350.1 C351.2 C353.1 C354.1 C356.1 C357.2 C358.2 C359.1 C361.2 C362.2 C367.2 C368.1 C369.2 C376.2 C377.2 C380.2 C382.2 C383.2 C388.2 C389.2 C390.2 C391.1 C392.2 C393.2 C394.2 C395.2 C396.1 C397.2 C398.2 C404.2 C405.2 C406.2 C407.2 C408.2 C414.2 C415.2 C416.1 C417.1 C418.1 C419.2 C420.2 C423.2 C424.2 C425.2 C431.1 C432.2 C434.1 C435.1 C436.2 C437.2 C439.2 C440.2 C441.1 C442.1 C443.1 C444.1 C445.1 C446.1 C447.1 C448.1 C449.1 C450.1 C451.1 C452.2 C453.2 C454.1 C455.1 C456.1 C457.2 C458.2 C460.1 C461.1 C462.2 C465.1 C466.1 C467.2 C468.2 C471.1 C472.1 C473.2 C474.1 C475.1 C476.1 C477.1 C478.2 C479.2 C482.2 C483.1 C484.1 C485.2 C486.2 C487.1 C488.1 C489.2 C490.1 C491.1 C492.2 C494.1 C495.2 C496.2 C497.2 C498.2 C499.1 C500.2 C501.1 C502.2 C503.2 C504.2 C505.2 C506.2 C507.1 C508.1 C509.2 C510.2 C511.2 C512.1 C513.2 C514.1 C515.1 C516.1 C517.2 C519.1 C520.2 C521.1 C522.2 C523.2 C524.2 C525.1 C527.1 C528.1 C529.2 C530.2 C531.2 C534.2 C535.2 C536.1 C538.2 C539.1 C540.2 C542.2 C543.2 C545.1 C546.1 C547.1 C548.2 C549.2 C550.2 C551.2 C552.1 C553.2 C554.2 C555.2 C556.2 C557.2 C558.2 C560.2 C561.2 C562.2 C563.2 C564.2 C565.1 C566.1 C567.2 C568.2 C569.2 C570.2 C571.1 C572.2 C573.2 C574.1 C575.2 C576.2 C577.2 C578.2 C579.1 C580.2 C581.2 C582.2 C583.2 C584.1 C585.2 C587.1 C588.2 C589.2 C590.2 C591.2 C592.2 C595.2 C596.2 C597.2 C598.2 C599.1 C600.1 C601.2 C605.2 C606.1 C607.2 C608.1 C609.1 C612.2 C613.2 C614.2 C615.1 C617.1 C618.2 C619.2 C620.2 C621.1 C622.1 C623.2 C624.2 C625.2 C626.2 C628.1 C629.2 C630.2 C631.2 C632.2 C633.1 C634.2 C635.2 C636.2 C637.2 C638.2 C639.1 C640.2 C641.1 C642.2 C644.2 C645.2 C646.2 C647.2 C648.2 C649.2 C650.2 C651.2 C652.2 C654.2 C655.2 C656.2 C657.2 C658.2 C667.2 C668.2 C669.2 C670.2 C671.2 C672.2 C673.2 C674.2 C678.2 C679.2 C681.2 C682.2 C683.2 C688.2 C689.2 C690.2 C691.2 C696.2 C697.2 C700.2 C706.2 C711.2 C712.2 C713.2 C714.2 C715.2 C716.2 C717.2 C718.2 C719.2 C720.2 C722.2 C725.1 C726.2 C727.2 C728.2 C729.2 C730.2 C731.2 C732.2 C733.2 C734.2 C735.2 C736.2 C746.2 C749.2 C750.2 C751.2 C752.2 C753.2 C775.1 C776.2 C782.2 C783.2 C784.2 C785.2 C786.2 C787.2 C790.2 CN1.5(2) CN1.6 CN1.7 CN1.8 CN2.5(2) CN2.6 CN2.7 CN2.8 CN3.5(2) CN3.6 CN3.7 CN3.8 CN4.5(2) CN4.6 CN4.7 CN4.8 CN5.5(2) CN5.6 CN5.7 CN5.8 CN6.5(2) CN6.6 CN6.7 CN6.8 CN7.5(2) CN7.6 CN7.7 CN7.8 CN8.5(2) CN8.6 CN8.7 CN8.8 CN9.5(2) CN9.6 CN9.7 CN9.8 CN10.5(2) CN10.6 CN10.7 CN10.8 CN11.5(2) CN11.6 CN11.7 CN11.8 CN12.5(2) CN12.6 CN12.7 CN12.8 CN13.5(2) CN13.6 CN13.7 CN13.8 CON3.1 CON3.25 CON3.33 CON3.39 CON3.50 HS1.1(HS1) J31.3 J31.7 J31.9 J31.13 J31.15 J31.16 J31.17 J34.39 J34.40 J34.41 J34.42 J34.43 J36.2 J36.4 J36.6 J36.8 J42.A2(GND9) J42.A5 J42.A8 J42.A11 J42.A14 J42.B2 J42.B5 J42.B8 J42.B11 J48.1 J55.1 J56.1 J57.A3 J57.A6 J57.A9 J57.A12 J57.A14 J57.A17 J57.A20 J57.A23 J57.A26 J57.B3 J57.B6 J57.B9 J57.B12 J57.B14 J57.B17 J57.B20 J57.B23 J57.B26 J58.A3 J58.A6 J58.A9 J58.A12 J58.A14 J58.A17 J58.A20 J58.A23 J58.A26 J58.B3 J58.B6 J58.B9 J58.B12 J58.B14 J58.B17 J58.B20 J58.B23 J58.B26 J59.A2(GND9) J59.A5 J59.A8 J59.A11 J59.A14 J59.B2 J59.B5 J59.B8 J59.B11 J63.2 J63.10 J75.39 J75.40 J75.41 J75.42 J75.43 J78.2 J78.4 J78.6 J78.8 J78.10 J78.12 J78.14 J78.16 J78.18 J78.20 J79.1 J85.2 J85.10 J87.2 J87.10 J90.1 J92.2 J92.19 J92.22 J92.24 J92.26 J92.30 J92.34 J92.40 J111.1 J112.1 J113.1 J114.1 J124.5 J124.14 J124.19 J124.20 J124.21 J124.22 PMCJN1.3 PMCJN1.11 PMCJN1.14 PMCJN1.15 PMCJN1.24 PMCJN1.25 PMCJN1.34 PMCJN1.35 PMCJN1.39 PMCJN1.44 PMCJN1.51 PMCJN1.56 PMCJN1.63 PMCJN2.6 PMCJN2.7 PMCJN2.18 PMCJN2.21 PMCJN2.30 PMCJN2.33 PMCJN2.37 PMCJN2.40 PMCJN2.44 PMCJN2.56 PMCJN2.59 PMCJN2.63 R3.1 R39.2 R53.2 R56.2 R76.1 R77.1 R102.2 R105.1 R106.1 R107.1 R108.1 R109.1 R110.1 R111.1 R112.1 R113.1 R114.1 R120.2 R125.2 R128.2 R129.1 R130.2 R132.2 R139.2 R141.2 R185.2 R223.1 R225.1 R242.2 R259.2 R262.1 R263.1 R264.1 R265.1 R266.1 R267.1 R268.1 R269.1 R282.1 R283.1 R284.1 R285.1 R286.2 R306.2 R307.2 R329.1 R338.1 R339.1 R340.1 R341.1 R350.1 R353.2 R357.2 RN15.1 RN15.2 RN15.3 RN15.4 RN15.5 RN15.6 RN15.7 RN15.8 RN16.1 RN16.2 RN16.3 RN16.4 RN16.5 RN16.6 RN16.7 RN16.8 RN17.1 RN17.2 RN17.3 RN17.4 RN17.5 RN17.6 RN17.7 RN17.8 RN18.1 RN18.2 RN18.3 RN18.4 RN18.5 RN18.6 RN18.7 RN18.8 RN19.1 RN19.2 RN19.3 RN19.4 RN19.5 RN19.6 RN19.7 RN19.8 RN20.3 RN20.4 RN20.5 RN20.6 RN20.7 U1.3 U1.6(TAB) U5.2 U5.6 U5.7 U5.8 U5.10 U7.A2 U7.A13 U7.A20 U7.A31 U7.AA14 U7.AA19 U7.AA21 U7.AB22 U7.AC5 U7.AC28 U7.AF9 U7.AF17 U7.AG6 U7.AH10 U7.AH23 U7.AH27 U7.AL1 U7.AL32 U7.AM2 U7.AM13 U7.AM20 U7.AM31 U7.B1 U7.B32 U7.E10 U7.E23 U7.F7 U7.F27 U7.G17 U7.J24 U7.K5 U7.K28 U7.L11 U7.M12 U7.M14 U7.M19 U7.N1 U7.N14 U7.N16 U7.N18 U7.N20 U7.N32 U7.P12 U7.P13 U7.P15 U7.P17 U7.P19 U7.P21 U7.R14 U7.R16 U7.R18 U7.R20 U7.T7 U7.T13 U7.T15 U7.T17 U7.T19 U7.U14 U7.U16 U7.U18 U7.U20 U7.V11 U7.V13 U7.V15 U7.V17 U7.V19 U7.V22 U7.V27 U7.W12 U7.W14 U7.W16 U7.W18 U7.W20 U7.Y1 U7.Y13 U7.Y15 U7.Y17 U7.Y19 U7.Y32 U8.5 U11.13 U11.19 U11.24 U11.39 U11.52 U11.57 U11.67 U11.72 U11.93 U11.103 U11.108 U11.117 U12.2 U12.6 U12.7 U12.8 U12.10 U14.1 U14.4 U14.7(PGND) U15.A2 U15.A10 U15.A23 U15.A31 U15.AA10 U15.AA16 U15.AA17 U15.AA23 U15.AB8 U15.AB25 U15.AC1 U15.AC32 U15.AD17 U15.AF17 U15.AG6 U15.AG27 U15.AH6 U15.AH8 U15.AH10 U15.AH12 U15.AH21 U15.AH23 U15.AH25 U15.AH27(VREF5B8) U15.AL1 U15.AL2 U15.AL31 U15.AL32 U15.AM2 U15.AM10 U15.AM23 U15.AM31 U15.B1 U15.B2 U15.B31 U15.B32 U15.E6 U15.E8 U15.E10 U15.E12 U15.E21 U15.E23 U15.E25 U15.E27 U15.F6 U15.F27 U15.H18 U15.H24 U15.J17 U15.K1 U15.K32 U15.L8 U15.L25 U15.M13 U15.M15 U15.M16 U15.M17 U15.M18 U15.M20 U15.N12 U15.N14 U15.N16 U15.N17 U15.N19 U15.N21 U15.P13 U15.P15 U15.P18 U15.P20 U15.R12 U15.R14 U15.R16 U15.R17 U15.R19 U15.R21 U15.T12 U15.T13 U15.T15 U15.T18 U15.T20 U15.T21 U15.U12 U15.U13 U15.U15 U15.U18 U15.U20 U15.U21 U15.V12 U15.V14 U15.V16 U15.V17 U15.V19 U15.V21 U15.W13 U15.W15 U15.W18 U15.W20 U15.Y14 U15.Y16 U15.Y17 U15.Y19 U17.3 U19.10 U19.20 U20.10 U20.15 U20.16 U20.20 U21.10 U21.20 U22.12 U23.12 U24.12 U25.4 U25.10 U25.15 U25.21 U25.28 U25.34 U25.39 U25.45 U26.4 U26.10 U26.15 U26.21 U26.28 U26.34 U26.39 U26.45 U28.15 U29.2 U29.41 U29.58 U29.69 U29.70 U29.71 U29.79 U30.2 U30.41 U30.58 U30.69 U30.70 U30.71 U30.79 U31.27 U31.46 U33.15 U34.4 U34.10 U34.15 U34.21 U34.26 U34.28 U34.34 U34.39 U34.45 U36.8 U36.10 U36.11 U36.14 U36.15 U36.17 U36.18 U36.19 U37.8 U37.10 U37.11 U37.14 U37.15 U37.17 U37.18 U37.19 U38.5 U38.6 U38.7 U38.8 U39.12 U43.8(VSS) U44.8(VSS) U45.4 U45.5 U52.12 U53.2 U60.2 XU2.2 XU2.5 XU2.8 XU2.11 XU2.14 XU2.17 XU2.20 XU2.23 XU2.26 XU2.29 XU2.32 XU2.35 XU2.38 XU2.41 XU2.44 XU2.47 XU2.50 XU2.65 XU2.66 XU2.79 XU2.82 XU2.85 XU2.88 XU2.91 XU2.94 XU2.97 XU2.100 XU2.101 XU2.103 XU2.106 XU2.109 XU2.112 XU2.115 XU2.118 XU2.121 XU2.124 XU2.127 XU2.130 XU2.133 XU2.136 XU2.139 XU2.142 XU2.145 XU2.148 XU2.151 XU2.154 XU2.157 XU2.160 XU2.163 XU2.166 XU2.169 XU2.198 XU2.201 XU2.204 XU2.207 XU2.210 XU2.213 XU2.216 XU2.219 XU2.222 XU2.225 XU2.228 XU2.231 XU2.234 XU2.237 XU2.239 XU2.240 Y4.3
GND_HSSI: C19.2 C33.2 C35.1 C41.2 C43.2 C44.2 C50.2 C51.2 C52.2 C53.2 C60.2 C72.2 C77.2 C80.2 C136.1 C137.2 C138.1 C139.1 C204.1 C205.1 C206.1 C207.1 C209.2 C210.2 C229.2 C230.1 C231.1 C236.2 C240.2 C243.2 C244.2 C249.2 C252.2 C282.2 C286.1 C290.1 C297.2 C303.2 C322.1 C326.2 C352.2 C355.1 C360.2 C363.2 C372.2 C373.2 C384.2 C387.1 C399.2 C402.2 C403.1 C421.2 C422.2 C426.2 C427.2 C428.2 C429.2 C430.2 C433.2 C464.2 C493.2 C518.2 C526.2 C532.2 C643.2 C653.2 C659.1 C660.2 C661.1 C662.2 C663.1 C664.1 C665.2 C666.2 C680.2 C684.2 C685.2 C686.2 C687.2 C692.2 C693.2 C694.2 C695.2 C699.2 C701.2 C721.2 C747.2 C748.2 C754.1 C755.1 C756.1 C757.1 C758.1 C759.1 C760.1 C761.1 C762.1 C763.1 C764.1 C765.1 C766.1 C767.1 C768.1 C769.1 C770.1 C771.1 C772.1 C773.1 C777.2 C778.1 C779.1 C780.1 C781.1 C788.2 C789.2 J1.1BG J1.1DG J1.1FG J1.1HG J1.2BG J1.2DG J1.2FG J1.2HG J1.3BG J1.3DG J1.3FG J1.3HG J1.4BG J1.4DG J1.4FG J1.4HG J1.5BG J1.5DG J1.5FG J1.5HG J1.6BG J1.6DG J1.6FG J1.6HG J1.7BG J1.7DG J1.7FG J1.7HG J1.8BG J1.8DG J1.8FG J1.8HG J1.9BG J1.9DG J1.9FG J1.9HG J1.10BG J1.10DG J1.10FG J1.10HG J2.2 J2.3 J2.4 J2.5 J3.2 J3.3 J3.4 J3.5 J4.2 J4.3 J4.5 J5.2 J5.3 J5.4 J5.5 J6.2 J6.3 J6.4 J6.5 J11.1 J11.4 J11.7 J11.8 J11.9 J11.10 J11.11 J11.12 J11.13 J15.1 J15.4 J15.7 J15.8 J15.9 J15.10 J15.11 J15.12 J15.13 J16.2 J16.3 J16.4 J16.5 J17.2 J17.3 J17.4 J17.5 J18.2 J18.3 J18.4 J18.5 J19.2 J19.3 J19.4 J19.5 J20.2 J20.3 J20.4 J20.5 J23.1 J23.4 J23.7 J23.8 J23.9 J23.10 J23.11 J23.12 J23.13 J24.2 J24.3 J24.4 J24.5 J25.2 J25.3 J25.4 J25.5 J26.2 J26.3 J26.4 J26.5 J27.2 J27.3 J27.4 J27.5 J28.2 J28.3 J28.4 J28.5 J29.2 J29.3 J29.4 J29.5 J30.2 J30.3 J30.4 J30.5 J32.1 J32.4 J32.7 J32.8 J32.9 J32.10 J32.11 J32.12 J32.13 J37.2 J37.3 J37.4 J37.5 J38.1 J38.9 J38.10 J38.11 J38.14 J38.17 J38.20(VEET3) J38.21 J38.22 J38.23 J38.24 J38.25 J38.26 J38.27 J38.28 J38.29 J38.30 J38.31 J38.32 J38.33 J38.34 J38.35 J38.36 J38.37 J38.38 J38.39 J38.40 J43.2 J43.3 J43.4 J43.5 J45.1 J45.9 J45.10 J45.11 J45.14 J45.17 J45.20(VEET3) J45.21 J45.22 J45.23 J45.24 J45.25 J45.26 J45.27 J45.28 J45.29 J45.30 J45.31 J45.32 J45.33 J45.34 J45.35 J45.36 J45.37 J45.38 J45.39 J45.40 J46.2 J46.3 J46.4 J46.5 J47.2 J47.3 J47.4 J47.5 J49.2 J49.3 J49.4 J49.5 J52.2 J52.3 J52.4 J52.5 J54.1 J54.9 J54.10 J54.11 J54.14 J54.17 J54.20(VEET3) J54.21 J54.22 J54.23 J54.24 J54.25 J54.26 J54.27 J54.28 J54.29 J54.30 J54.31 J54.32 J54.33 J54.34 J54.35 J54.36 J54.37 J54.38 J54.39 J54.40 J60.2 J60.3 J60.4 J60.5 J61.2 J61.3 J61.4 J61.5 J62.2 J62.3 J62.4 J62.5 J64.1 J64.9 J64.10 J64.11 J64.14 J64.17 J64.20(VEET3) J64.21 J64.22 J64.23 J64.24 J64.25 J64.26 J64.27 J64.28 J64.29 J64.30 J64.31 J64.32 J64.33 J64.34 J64.35 J64.36 J64.37 J64.38 J64.39 J64.40 J69.2 J69.3 J69.4 J69.5 J72.2 J72.3 J72.4 J72.5 J72.6 J72.7 J72.8 J72.9 J72.10 J72.11 J72.12 J72.13 J72.14 J72.15 J72.16 J72.17 J72.18 J72.19 J72.20 J72.21 J72.22 J72.23 J72.24 J72.25 J72.26 J72.27 J72.28 J72.29 J72.30 J72.31 J72.32 J72.33 J72.34 J72.35 J76.2 J76.3 J76.4 J76.5 J77.2 J77.3 J77.4 J77.5 J77.6 J77.7 J77.8 J77.9 J77.10 J77.11 J77.12 J77.13 J77.14 J77.15 J77.16 J77.17 J77.18 J77.19 J77.20 J77.21 J77.22 J77.23 J77.24 J77.25 J77.26 J77.27 J77.28 J77.29 J77.30 J77.31 J77.32 J77.33 J77.34 J77.35 J80.2 J80.3 J80.4 J80.5 J81.2 J81.3 J81.4 J81.5 J81.6 J81.7 J81.8 J81.9 J81.10 J81.11 J81.12 J81.13 J81.14 J81.15 J81.16 J81.17 J81.18 J81.19 J81.20 J81.21 J81.22 J81.23 J81.24 J81.25 J81.26 J81.27 J81.28 J81.29 J81.30 J81.31 J81.32 J81.33 J81.34 J81.35 J83.2 J83.3 J83.4 J83.5 J84.2 J84.3 J84.4 J84.5 J86.2 J86.3 J86.4 J86.5 J86.6 J86.7 J86.8 J86.9 J86.10 J86.11 J86.12 J86.13 J86.14 J86.15 J86.16 J86.17 J86.18 J86.19 J86.20 J86.21 J86.22 J86.23 J86.24 J86.25 J86.26 J86.27 J86.28 J86.29 J86.30 J86.31 J86.32 J86.33 J86.34 J86.35 J88.2 J88.3 J88.4 J88.5 J89.2 J89.3 J89.4 J89.5 J91.2 J91.3 J91.4 J91.5 J93.2 J93.3 J93.4 J93.5 J93.6 J93.7 J93.8 J93.9 J93.10 J93.11 J93.12 J93.13 J93.14 J93.15 J93.16 J93.17 J93.18 J93.19 J93.20 J93.21 J93.22 J93.23 J93.24 J93.25 J93.26 J93.27 J93.28 J93.29 J93.30 J93.31 J93.32 J93.33 J93.34 J93.35 J94.2 J94.3 J94.4 J94.5 J95.2 J95.3 J95.4 J95.5 J97.2 J97.3 J97.4 J97.5 J98.2 J98.3 J98.4 J98.5 J98.6 J98.7 J98.8 J98.9 J98.10 J98.11 J98.12 J98.13 J98.14 J98.15 J98.16 J98.17 J98.18 J98.19 J98.20 J98.21 J98.22 J98.23 J98.24 J98.25 J98.26 J98.27 J98.28 J98.29 J98.30 J98.31 J98.32 J98.33 J98.34 J98.35 J99.2 J99.3 J99.4 J99.5 J100.2 J100.3 J100.4 J100.5 J101.2 J101.3 J101.4 J101.5 J101.6 J101.7 J101.8 J101.9 J101.10 J101.11 J101.12 J101.13 J101.14 J101.15 J101.16 J101.17 J101.18 J101.19 J101.20 J101.21 J101.22 J101.23 J101.24 J101.25 J101.26 J101.27 J101.28 J101.29 J101.30 J101.31 J101.32 J101.33 J101.34 J101.35 J102.2 J102.3 J102.4 J102.5 J103.2 J103.3 J103.4 J103.5 J104.2 J104.3 J104.4 J104.5 J105.2 J105.3 J105.4 J105.5 J105.6 J105.7 J105.8 J105.9 J105.10 J105.11 J105.12 J105.13 J105.14 J105.15 J105.16 J105.17 J105.18 J105.19 J105.20 J105.21 J105.22 J105.23 J105.24 J105.25 J105.26 J105.27 J105.28 J105.29 J105.30 J105.31 J105.32 J105.33 J105.34 J105.35 J106.2 J106.3 J106.4 J106.5 J107.2 J107.3 J107.4 J107.5 J108.1DG J108.1FG J108.1HG J108.2BG J108.2DG J108.2FG J108.2HG J108.3BG J108.3DG J108.3FG J108.3HG J108.4BG J108.4DG J108.4FG J108.4HG J108.5BG J108.5DG J108.5FG J108.5HG J108.6BG J108.6DG J108.6FG J108.6HG J108.7BG J108.7DG J108.7FG J108.7HG J108.8BG J108.8DG J108.8FG J108.8HG J108.9BG J108.9DG J108.9FG J108.9HG J108.10BG J108.10DG J108.10FG J108.10HG J109.1BG J109.1DG J109.1FG J109.1HG J109.2BG J109.2DG J109.2FG J109.2HG J109.3BG J109.3DG J109.3FG J109.3HG J109.4BG J109.4DG J109.4FG J109.4HG J109.5BG J109.5DG J109.5FG J109.5HG J109.6BG J109.6DG J109.6FG J109.6HG J109.7BG J109.7DG J109.7FG J109.7HG J109.8BG J109.8DG J109.8FG J109.8HG J109.9BG J109.9DG J109.9FG J109.9HG J109.10BG J109.10DG J109.10FG J109.10HG J121.2 J121.3 J121.4 J121.5 J122.2 J122.3 J122.4 J122.5 J123.3 J123.4 R5.1 R16.1 R17.1 R21.1 R27.1 R32.1 R34.1 R35.1 R40.1 R46.1 R47.1 R48.2 R88.1 R89.1 R92.1 R93.1 R176.1 R177.1 R191.1 R194.1 R196.2 R298.1 R348.1 U4.5 U6.11 U9.5 U10.7 U10.8 U10.11 U10.15 U10.20 U10.24 U10.27 U10.31 U13.4 U18.1 U18.9 U18.13 U27.1 U27.2 U27.3 U27.33 U27.34 U27.35 U27.36 U27.37 U27.40 U27.43 U27.46 U27.49 U27.52 U27.53 U27.54 U27.57 U27.60 U27.63 U27.66 U27.69 U27.70 U32.1 U32.9 U32.13 U42.3 U42.6(TAB) U46.5(VSS) U47.5(VSS) Y1.2 Y2.2 Y3.2
GND_PLL: C45.2 C46.2 C47.2 C84.2 C85.2 C89.2 C91.2 C287.1 C295.1 C314.2 C329.2 C364.2 C365.2 C366.2 C370.1 C371.1 C374.2 C375.1 C378.2 C379.1 C381.2 C385.2 C386.1 C400.2 C401.2 C409.1 C410.2 C411.2 C412.2 C413.2 C438.2 C459.2 C463.2 C469.2 C470.1 C480.1 C481.2 C533.2 C537.1 C541.1 C544.2 C559.2 C586.2 C593.1 C594.1 C602.2 C603.1 C604.1 C610.2 C611.2 C616.2 C627.2 C698.2 U15.A15 U15.AB4 U15.AB5 U15.AB16 U15.AB28 U15.AB29 U15.AE16 U15.AH3 U15.AH16 U15.AH17 U15.AH30 U15.AJ1 U15.AJ15 U15.AJ19 U15.AJ32 U15.AK15 U15.AL15 U15.AL17 U15.AL19 U15.AM15 U15.AM17 U15.AM19 U15.B19 U15.C15 U15.C17 U15.D1 U15.D15 U15.D17 U15.D32 U15.E3 U15.E17 U15.E30 U15.F17 U15.H15 U15.L4 U15.L5 U15.L16 U15.L28 U15.L29 U15.T3 U15.T4 U15.T5 U15.T6 U15.T7 U15.T22 U15.T24 U15.T26 U15.U3 U15.U4 U15.U7 U15.U9 U15.U11 U15.U26 U15.U29 U15.U30 U15.U31 U15.U32
GND_RTN: C48.1 C100.1 C124.1 R207.2 U8.1 U45.1
GNDA_PLL1: U7.T25 U7.T26
GNDA_PLL2: U7.U25 U7.U26
GNDA_PLL3: U7.U8 U7.V8
GNDA_PLL4: U7.R8 U7.T8
GNDA_PLL5: U7.G16 U7.H16
GNDA_PLL6: U7.AD16 U7.AE16
GNDA_PLL7: U7.F26 U7.G26
GNDA_PLL8: U7.AG26 U7.AG27
GNDA_PLL9: U7.AF7 U7.AG7
GNDA_PLL10: U7.G7 U7.G8
GNDA_PLL11: U7.G18 U7.H18
GNDA_PLL12: U7.AD17 U7.AE17
V0_9: CN1.1 CN1.2 CN1.3 CN1.4 CN2.1 CN2.2 CN2.3 CN2.4 CN3.1 CN3.2 CN3.3 CN3.4 CN4.1 CN4.2 CN4.3 CN4.4 CN5.1 CN5.2 CN5.3 CN5.4 CN6.1 CN6.2 CN6.3 CN6.4 CN7.1 CN7.2 CN7.3 CN7.4 CN8.1 CN8.2 CN8.3 CN8.4 CN9.1 CN9.2 CN9.3 CN9.4 CN10.1 CN10.2 CN10.3 CN10.4 CN11.1 CN11.2 CN11.3 CN11.4 CN12.1 CN12.2 CN12.3 CN12.4 CN13.1 CN13.2 CN13.3 CN13.4 R1.1 R7.2 R11.2 R23.2 R30.2 R70.2 R73.2 R136.1 R236.2 R238.2 RN5.9(2) RN5.10 RN5.11 RN5.12 RN5.13 RN5.14 RN5.15 RN5.16 RN23.1 RN23.2 RN23.3 RN23.4 RN23.5 RN23.6 RN23.7 RN23.8 RN24.1 RN24.2 RN24.3 RN24.4 RN24.5 RN24.6 RN24.7 RN24.8 RN25.1 RN25.2 RN25.3 RN25.4 RN25.5 RN25.6 RN25.7 RN25.8 RN26.1 RN26.2 RN26.3 RN26.4 RN26.5 RN26.6 RN26.7 RN26.8 RN27.10 RN27.11 RN27.12 RN27.13 RN27.14 RN27.15 RN27.16 RN28.1 RN28.2 RN28.3 RN28.4 RN28.5 RN28.6 RN28.7 RN28.8 RN29.9(2) RN29.10 RN29.11 RN29.12 RN29.13 RN29.14 RN29.15 RN29.16 RN30.1 RN30.2 RN30.3 RN30.4 RN30.5 RN30.6 RN30.7 RN30.8 RN31.1 RN31.2 RN31.3 RN31.4 RN31.5 RN31.6 RN31.7 RN31.8 RN32.1 RN32.2 RN32.3 RN32.4 RN32.5 RN32.6 RN32.7 RN32.8
VCCA: C87.1 C88.1 RJ1.2
VCCA_PLL1: U7.T24
VCCA_PLL2: U7.V26
VCCA_PLL3: U7.U9
VCCA_PLL4: U7.R9
VCCA_PLL5: U7.G15
VCCA_PLL6: U7.AE15
VCCA_PLL7: U7.H26
VCCA_PLL8: U7.AF26
VCCA_PLL9: U7.AE7
VCCA_PLL10: U7.H8
VCCA_PLL11: U7.H17
VCCA_PLL12: U7.AF18
VCCD_PLL1: U7.U24
VCCD_PLL2: U7.V25
VCCD_PLL3: U7.U7
VCCD_PLL4: U7.T9
VCCD_PLL5: U7.H15
VCCD_PLL6: U7.AD15
VCCD_PLL7: U7.H25
VCCD_PLL8: U7.AF25
VCCD_PLL9: U7.AE8
VCCD_PLL10: U7.H7
VCCD_PLL11: U7.J18
VCCD_PLL12: U7.AE18
VCCINT: U7.AA12 U7.AC10 U7.K10 U7.K23 U7.M21 U7.N13 U7.N15 U7.N17 U7.N19 U7.P14 U7.P16 U7.P18 U7.P20 U7.R13 U7.R15 U7.R17 U7.R19 U7.T14 U7.T16 U7.T18 U7.T20 U7.U13 U7.U15 U7.U17 U7.U19 U7.V14 U7.V16 U7.V18 U7.V20 U7.W13 U7.W15 U7.W17 U7.W19 U7.W21 U7.Y14 U7.Y16 U7.Y18 U7.Y20
VCCPD1: U7.V21 U7.Y21
VCCPD2: U7.N21 U7.R21
VCCPD3: U7.M18 U7.M20
VCCPD4: U7.M13 U7.M15
VCCPD5: U7.N12 U7.R12
VCCPD6: U7.V12 U7.Y12
VCCPD7: U7.AA13 U7.AA15
VCCPD8: U7.AA18 U7.AA20
VCCQP: C425.1 R300.2 U37.13
VDDQ: C720.1 R326.2 U53.5
APS: C564.1 C567.1
APS_INPUT: C86.1 C95.1 R115.1 R122.1 U14.5 U17.7 U17.8
APS_SENSE: R115.2 R247.1 U27.27
APS_SET: R248.1 U27.25
APS_XPAK: C12.1 C706.1 U27.7 U27.8 U27.28 U27.29
BRIDGE_RX_N<0>: J59.A3 U7.N31 U15.R5
BRIDGE_RX_N<1>: J59.B1 U7.N29 U15.G6
BRIDGE_RX_N<2>: J59.A6 U7.M32 U15.H8
BRIDGE_RX_N<3>: J59.B4 U7.M30 U15.H5
BRIDGE_RX_N<4>: J59.A9 U7.L32 U15.J7
BRIDGE_RX_N<5>: J59.B7 U7.L30 U15.J5
BRIDGE_RX_N<6>: J59.A12 U7.K32 U15.K8
BRIDGE_RX_N<7>: J59.B10 U7.K30 U15.K5
BRIDGE_RX_N<8>: U7.J32 U15.M6
BRIDGE_RX_N<9>: U7.H32 U15.M8
BRIDGE_RX_N<10>: U7.H30 U15.N10
BRIDGE_RX_N<11>: U7.G32 U15.N5
BRIDGE_RX_N<12>: U7.G30 U15.P9
BRIDGE_RX_N<13>: U7.F32 U15.N7
BRIDGE_RX_N<14>: U7.F30 U15.P6
BRIDGE_RX_N<15>: U7.E32 U15.R10
BRIDGE_RX_P<0>: J59.A1 U7.N30 U15.R6
BRIDGE_RX_P<1>: J59.B3 U7.N28 U15.G5
BRIDGE_RX_P<2>: J59.A4 U7.M31 U15.H7
BRIDGE_RX_P<3>: J59.B6 U7.M29 U15.H6
BRIDGE_RX_P<4>: J59.A7 U7.L31 U15.J8
BRIDGE_RX_P<5>: J59.B9 U7.L29 U15.J6
BRIDGE_RX_P<6>: J59.A10 U7.K31 U15.K7
BRIDGE_RX_P<7>: J59.B12 U7.K29 U15.K6
BRIDGE_RX_P<8>: U7.J31 U15.M7
BRIDGE_RX_P<9>: U7.H31 U15.M9
BRIDGE_RX_P<10>: U7.H29 U15.N9
BRIDGE_RX_P<11>: U7.G31 U15.N6
BRIDGE_RX_P<12>: U7.G29 U15.P10
BRIDGE_RX_P<13>: U7.F31 U15.N8
BRIDGE_RX_P<14>: U7.F29 U15.P5
BRIDGE_RX_P<15>: U7.E31 U15.R9
BRIDGE_RXCLK_N: J59.A15 R60.1 U15.L6
BRIDGE_RXCLK_P: J59.A13 R60.2 U15.L7
BRIDGE_TX_N<0>: J42.A3 U7.W29 U15.W2
BRIDGE_TX_N<1>: J42.B1 U7.W27 U15.W4
BRIDGE_TX_N<2>: J42.A6 U7.W25 U15.Y2
BRIDGE_TX_N<3>: J42.B4 U7.V29 U15.Y4
BRIDGE_TX_N<4>: J42.A9 U7.V24 U15.AA3
BRIDGE_TX_N<5>: J42.B7 U7.U28 U15.AB3
BRIDGE_TX_N<6>: J42.A12 U7.U23 U15.AA4
BRIDGE_TX_N<7>: J42.B10 U7.AE28 U15.AC2
BRIDGE_TX_N<8>: U7.AD27 U15.AD3
BRIDGE_TX_N<9>: U7.AD25 U15.AC3
BRIDGE_TX_N<10>: U7.AC27 U15.AE2
BRIDGE_TX_N<11>: U7.AC25 U15.AE4
BRIDGE_TX_N<12>: U7.AB26 U15.AF2
BRIDGE_TX_N<13>: U7.AB24 U15.AF4
BRIDGE_TX_N<14>: U7.AA27 U15.AG1
BRIDGE_TX_N<15>: U7.AA25 U15.AG4
BRIDGE_TX_P<0>: J42.A1 U7.W28 U15.W1
BRIDGE_TX_P<1>: J42.B3 U7.W26 U15.W3
BRIDGE_TX_P<2>: J42.A4 U7.W24 U15.Y1
BRIDGE_TX_P<3>: J42.B6 U7.V28 U15.Y3
BRIDGE_TX_P<4>: J42.A7 U7.V23 U15.AA2
BRIDGE_TX_P<5>: J42.B9 U7.U27 U15.AB2
BRIDGE_TX_P<6>: J42.A10 U7.U22 U15.AA5
BRIDGE_TX_P<7>: J42.B12 U7.AE27 U15.AB1
BRIDGE_TX_P<8>: U7.AD26 U15.AD4
BRIDGE_TX_P<9>: U7.AD24 U15.AC4
BRIDGE_TX_P<10>: U7.AC26 U15.AE1
BRIDGE_TX_P<11>: U7.AC24 U15.AE3
BRIDGE_TX_P<12>: U7.AB25 U15.AF1
BRIDGE_TX_P<13>: U7.AB23 U15.AF3
BRIDGE_TX_P<14>: U7.AA26 U15.AG2
BRIDGE_TX_P<15>: U7.AA24 U15.AG3
BRIDGE_TXCLK_N: J42.A15 R323.1 U7.AE26 U15.U1
BRIDGE_TXCLK_P: J42.A13 R323.2 U7.AE25 U15.U2
BST: C92.1 U14.10
BUS_CONV_5V: C102.1 C103.2 C587.2 C588.1 C639.2 C640.1 C641.2 C642.1 U22.24(VCC) U23.24(VCC) U24.24(VCC) U39.24(VCC) U52.24(VCC)
CE_S_N: U15.AF18
CEO_S_N: U15.AH15
CF_ATASEL_N: U15.H11 U52.6
CF_CS_N: U15.K12 U52.10
CF_POWER: U15.F12 U52.2
CF_PRESENT_N: U15.J12 U52.9
CF_REG: U15.K13 U52.4
CF_RESET_N: U15.H12 U52.7
CLK_25MHZ: U11.127 Y4.4
CLK_DIV_A: J55.2 R74.2 U10.5
CLK_DIV_B: J56.2 R75.2 U10.6
CLK_EN1: R172.1 U32.3 Y3.1
CLK_EN2: R159.1 U18.3 Y2.1
CLK_FROM_SCRUZ: J78.13 U15.B15
CLK_MR: C745.2 R225.2 U10.32
CLK_OUT_B: J47.1(OUTPUT) U10.19
CLK_SOURCE1: U32.6 Y3.3
CLK_SOURCE2: U18.6 Y2.3
CLK_TO_SCRUZ: J78.11 U15.AL18
COMP: C82.1 R117.2 U14.2
CRC_ERROR: U15.AF20
DATA_GEN_CLK_INN: C30.1 J29.1(OUTPUT)
DATA_GEN_CLK_INP: C31.1 J30.1(OUTPUT)
DEV1_CDONE_N: U19.13 U29.60
DEV1_CONFIG_N: U19.14 U29.16
DEV1_D0: R277.2 U19.16
DEV1_D1: R275.2 U19.17
DEV1_D2: R272.2 U19.18
DEV1_D3: R273.2 U19.19
DEV1_D4: R150.2 U20.2
DEV1_D5: R151.2 U20.3
DEV1_D6: R152.2 U20.4
DEV1_D7: R153.2 U20.5
DEV1_DCLK: U19.12 U29.11
DEV1_STATUS_N: U19.15 U29.23
DEV2_CDONE_N: U21.13 U30.60
DEV2_CONFIG_N: U21.14 U30.16
DEV2_D<0>: R276.2 U21.16
DEV2_D<1>: R274.2 U21.17
DEV2_D<2>: R270.2 U21.18
DEV2_D<3>: R271.2 U21.19
DEV2_D<4>: R154.2 U20.6
DEV2_D<5>: R155.2 U20.7
DEV2_D<6>: R156.2 U20.8
DEV2_D<7>: R157.2 U20.9
DEV2_DCLK: U21.12 U30.11
DEV2_STATUS_N: U21.15 U30.23
DH: U14.8 U17.2
DIFF_RX_DRSCLK_N: J109.8H U7.Y3
DIFF_RX_DRSCLK_P: J109.8G U7.Y2
